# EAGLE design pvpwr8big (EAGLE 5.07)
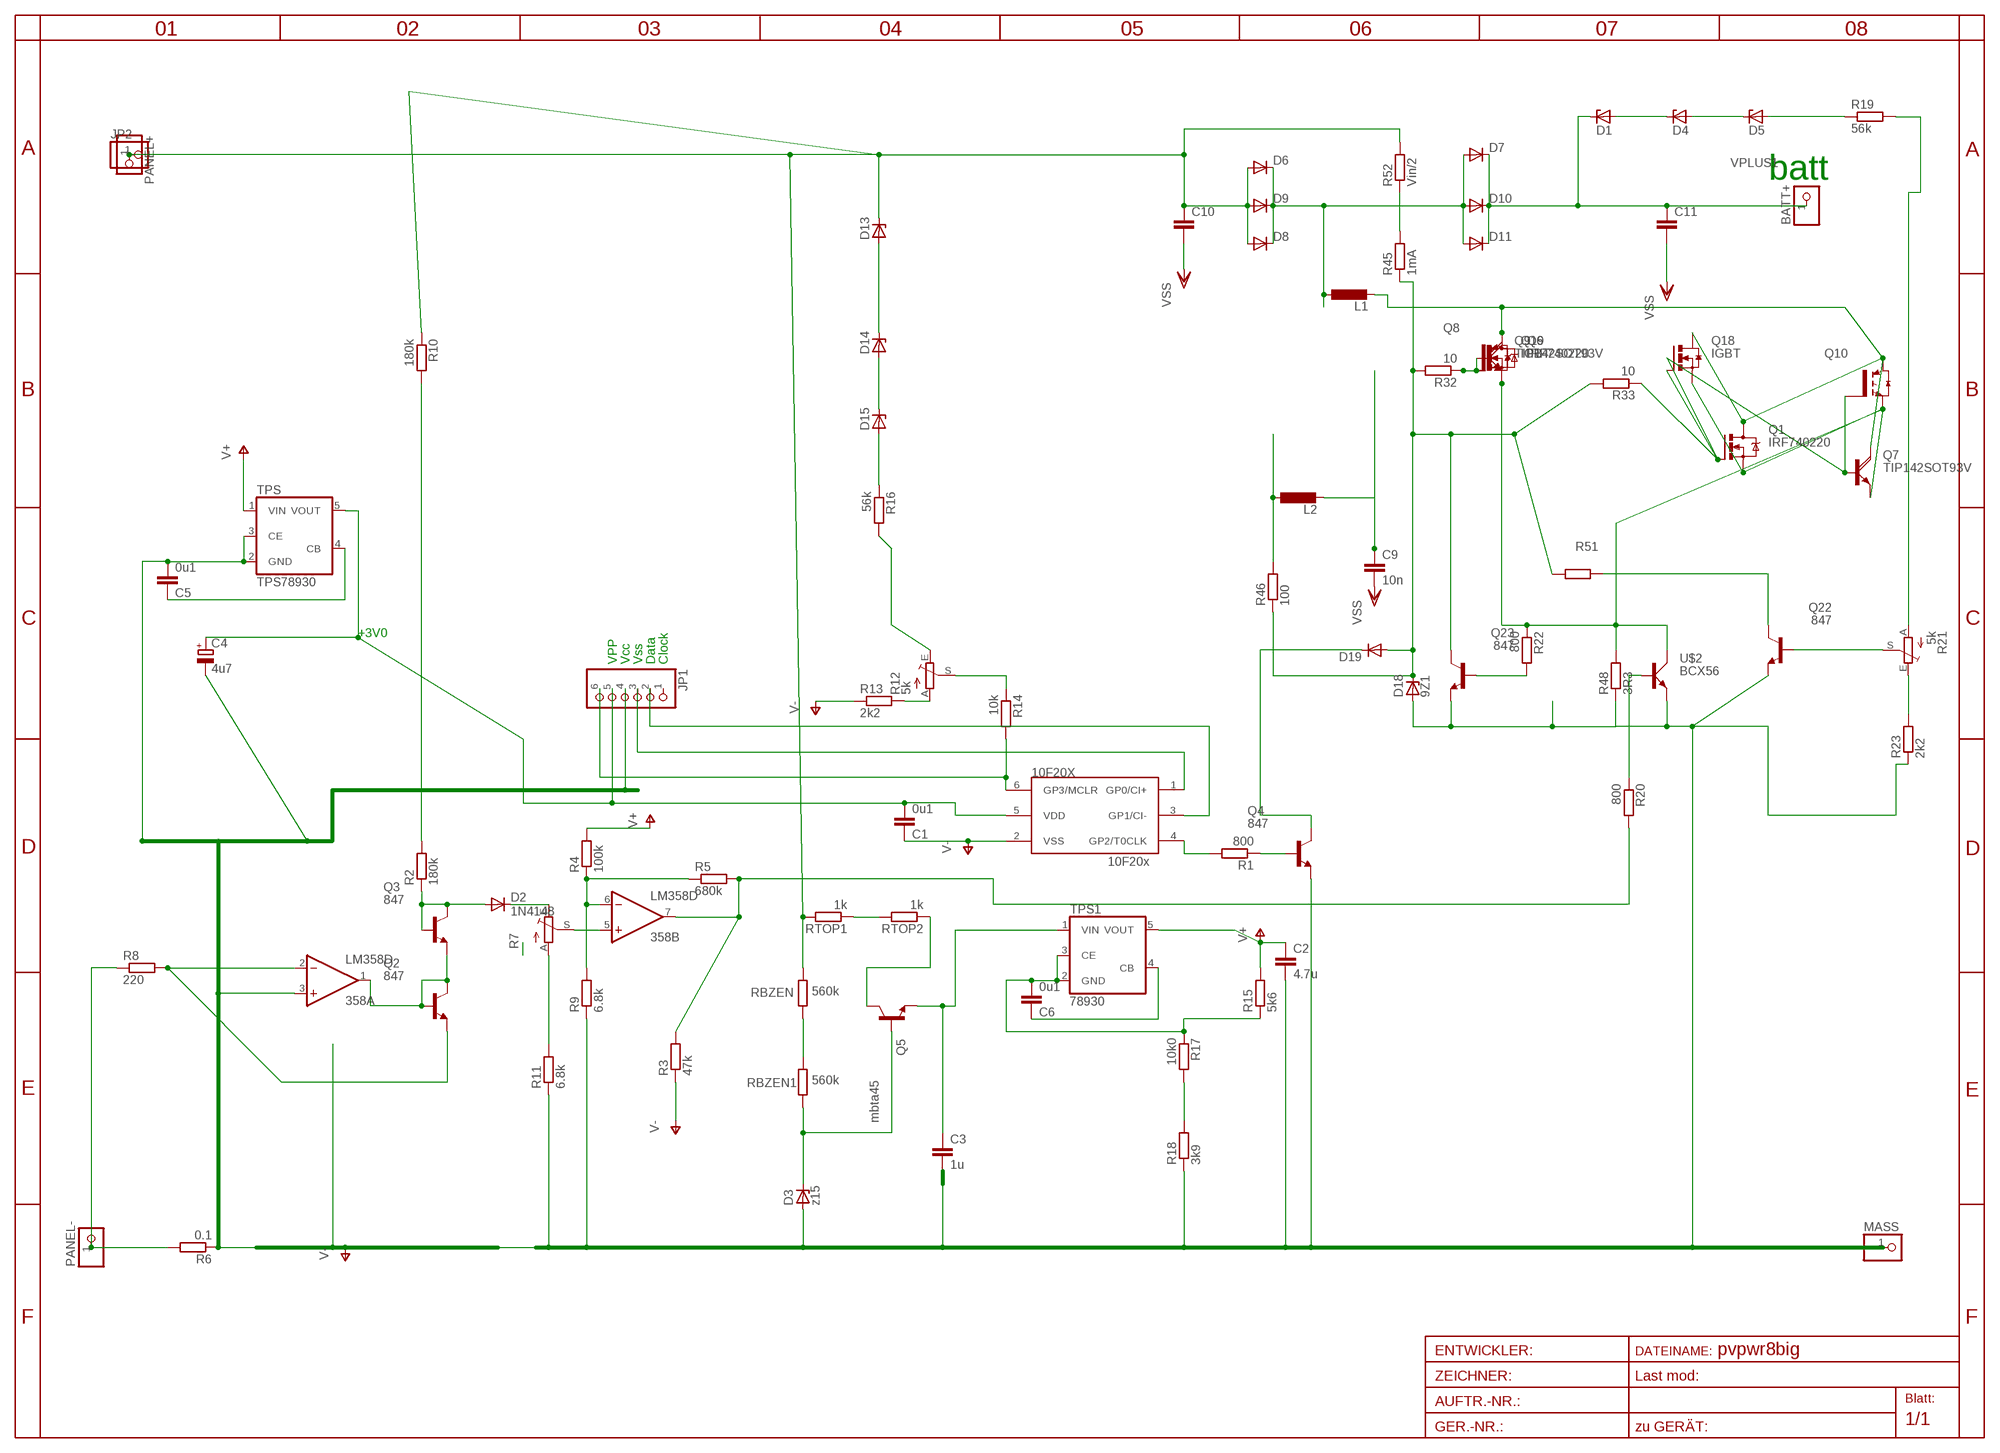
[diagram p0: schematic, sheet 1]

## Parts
10F20X  10F20x  PIC10F204OT  [SOT23-6]
358  LM358D  [SO08]
BATT+  PINHD-1X12MM2  [1X2MM2]
C1  0u1  C-EUC1206  [C1206]
C2  4.7u  C-EUC1206  [C1206]
C3  1u  C-EUC1206  [C1206]
C4  4u7  CPOL-EUSMCA  [SMC_A]
C5  0u1  C-EUC0805  [C0805]
C6  0u1  C-EUC0805  [C0805]
C9  10n  C-EUC0805  [C0805]
C10  C-EU075-052X106  [C075-052X106]
C11  C-EU075-052X106  [C075-052X106]
D1  ZENER-DIODESOD80C  [SOD80C]
D2  1N4148  DIODE-SOD80C  [SOD80C]
D3  z15  ZENER-DIODESOD80C  [SOD80C]
D4  ZENER-DIODESOD80C  [SOD80C]
D5  ZENER-DIODESOD80C  [SOD80C]
D6  DIODE-SMC  [SMC]
D7  DIODE-SMC  [SMC]
D8  DIODE-SMC  [SMC]
D9  DIODE-SMC  [SMC]
D10  DIODE-SMC  [SMC]
D11  DIODE-SMC  [SMC]
D13  ZENER-DIODESOD80C  [SOD80C]
D14  ZENER-DIODESOD80C  [SOD80C]
D15  ZENER-DIODESOD80C  [SOD80C]
D18  9Z1  ZENER-DIODESOD80C  [SOD80C]
D19  DIODE-MINIMELF  [MINIMELF]
JP1  PINHD-1X6  [1X06BOX]
JP2  PINHD-1X12MM2  [1X2MM2]
L1  L-EU4.13  [0204/13]
L2  L-EU0207/7  [0207/7]
MASS  PINHD-1X12MM2  [1X2MM2]
PANEL+  PINHD-1X11MM6  [1X1MM8]
PANEL-  PINHD-1X12MM2  [1X2MM2]
Q1  IRF740220  [TO220BV]
Q2  847  BC847ALT1SMD  [SOT23]
Q3  847  BC847ALT1SMD  [SOT23]
Q4  847  BC847ALT1SMD  [SOT23]
Q5  mbta45  BC847ALT1SMD  [SOT23]
Q6  IRF740220  [TO220BV]
Q7  TIP142SOT93V  [SOT93V]
Q8  IRG4BC15UD-S  [D2PACK]
Q9  TIP142SOT93V  [SOT93V]
Q10  IRG4BC15UD-S  [D2PACK]
Q18  IGBT  N-HEXFET_DPAK-  [TO252]
Q19  IGBT  N-HEXFET_DPAK-  [TO252]
Q22  847  BC847ASMD  [SOT23]
Q23  847  BC847ASMD  [SOT23]
R1  800  R-EU_R0805  [R0805]
R2  180k  R-EU_0207/15  [0207/15]
R3  47k  R-EU_R0805  [R0805]
R4  100k  R-EU_R1206  [R1206]
R5  680k  R-EU_R0805  [R0805]
R6  0.1  R-EU_R2512  [R2512]
R7  TRIM_EU-S64W  [S64W]
R8  220  R-EU_R0805  [R0805]
R9  6.8k  R-EU_R1206  [R1206]
R10  180k  R-EU_R1206  [R1206]
R11  6.8k  R-EU_R0805  [R0805]
R12  5k  TRIM_EU-S64W  [S64W]
R13  2k2  R-EU_R0805  [R0805]
R14  10k  R-EU_R0805  [R0805]
R15  5k6  R-EU_R0805  [R0805]
R16  56k  R-EU_R0805  [R0805]
R17  10k0  R-EU_R0805  [R0805]
R18  3k9  R-EU_R0805  [R0805]
R19  56k  R-EU_R0805  [R0805]
R20  800  R-EU_R0805  [R0805]
R21  5k  TRIM_EU-S64W  [S64W]
R22  800  R-EU_0207/12  [0207/12]
R23  2k2  R-EU_R0805  [R0805]
R32  10  R-EU_R0805  [R0805]
R33  10  R-EU_R0805  [R0805]
R45  1mA  R-EU_R1206  [R1206]
R46  100  R-EU_R0805  [R0805]
R48  3R3  R-EU_R2010  [R2010]
R51  39k  R-EU_R0805  [R0805]
R52  Vin/2  R-EU_R1206  [R1206]
RBZEN  560k  R-EU_R1206  [R1206]
RBZEN1  560k  R-EU_R1206  [R1206]
RTOP1  1k  R-EU_R1206  [R1206]
RTOP2  1k  R-EU_R1206  [R1206]
TPS  TPS78930  TPS78930SOT23-5  [SOT25]
TPS1  78930  TPS78930SOT23-5  [SOT25]
U$2  BCX56  [SOT223]

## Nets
BOOST_EN: D19.C Q4.3(C)
CB: D3.C Q5.1(B) RBZEN1.2
DQ18: L1.2 Q1.D Q6.D Q7.C Q8.2(C) Q9.C Q10.2(C) Q18.3(D) Q19.3(D)
GND1: C6.1 TPS1.4(CB)
IN-: PANEL-.1 R6.2 R8.1
N$1: Q4.1(B) R1.1
N$2: R7.A R11.2
N$4: 10F20X.1(GP0/CI+) JP1.3
N$5: 10F20X.4(GP2/T0CLK) R1.2
N$6: R2.2 R10.2
N$7: 358.1(A:OUT) Q2.1(B) Q2.3(C) Q3.2(E)
N$8: 10F20X.3(GP1/CI-) JP1.2
N$9: 10F20X.5(VDD) C1.2 C4.+ JP1.5 TPS.5(VOUT)
N$10: 358.2(A:-IN) Q2.2(E) R8.2
N$11: C5.1 TPS.4(CB)
N$12: D2.A Q3.1(B) Q3.3(C) R2.1
N$13: D2.C R7.E
N$15: 358.5(B:+IN) R7.S
N$16: Q5.3(C) RTOP2.1
N$17: 358.6(B:-IN) R4.1 R5.1 R9.2
N$18: D15.A R16.1
N$19: RBZEN1.1 RBZEN.2
N$20: D18.C D19.A Q23.3(C) R32.2 R33.2 R45.1 R46.1 R51.1
N$21: Q23.1(B) R22.2
N$22: D5.A R19.1
N$23: D14.A D15.C
N$24: D13.A D14.C
N$25: R12.E R16.2
N$26: R12.A R13.2
N$27: R12.S R14.1
N$28: R17.2 R18.2
N$29: RTOP1.1 RTOP2.2
N$30: D4.A D5.C
N$31: D1.A D4.C
N$32: R19.2 R21.A
N$33: 358.7(B:OUT) R3.2 R5.2 R20.2
N$34: R21.E R23.2
N$56: Q1.G Q7.B Q10.1(G) Q18.1(G) R33.1
N$58: Q6.G Q8.1(G) Q9.B Q19.1(G) R32.1
N$64: L2.1 R46.2
N$71: Q22.3(C) R51.2
N$74: C9.1 L2.2
N$80: R45.2 R52.1
N$89: R20.1 U$2.1(B)
NODOTL2: D6.C D7.A D8.C D9.C D10.A D11.A L1.1
PIR: 10F20X.6(GP3/MCLR) JP1.6 R14.2
PRB1: Q22.1(B) R21.S
SFET1: Q1.S Q6.S Q7.E Q8.3(E) Q9.E Q10.3(E) Q18.2(S) Q19.2(S) R22.1 R48.2 U$2.2(C)
V15: C3.1 Q5.2(E) TPS1.1(VIN)
V+: C2.1 R4.2 R15.2 TPS1.5(VOUT) TPS.1(VIN)
V-: 10F20X.2(VSS) 358.3(A:+IN) C1.1 C2.2 C3.2 C4.- C5.2 C9.2 C10.2 C11.2 D3.A D18.A JP1.4 MASS.1 Q4.2(E) Q22.2(E) Q23.2(E) R3.1 R6.1 R9.1 R11.1 R13.1 R18.1 R23.1 R48.1 TPS.2(GND) TPS.3(CE) U$2.3(E) ; supply symbol labelled VSS
VPLUS: C10.1 D6.A D8.A D9.A D13.C JP2.1 PANEL+.1 R10.1 R52.2 RBZEN.1 RTOP1.2
VPLUS1: BATT+.1 C11.1 D1.C D7.C D10.C D11.C
X: C6.2 R15.1 R17.1 TPS1.2(GND) TPS1.3(CE)
Unconnected: JP1.1

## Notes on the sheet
- batt
- +3V0
- VPP | Vcc | Vss | Data | Clock

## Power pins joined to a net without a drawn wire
V+: 358.8(P:V+)
V-: 358.4(P:V-)

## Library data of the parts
10F20X = microchip-3:PIC10F2*: uPC nW 0,25/0,5k Program Flash memory Comparator
358 = linear:LM358: OP AMP also LM158; LM258; LM2904 Source: http://cache.national.com/ds/LM/LM158.pdf
BATT+ JP2 MASS PANEL+ PANEL- = pinhead:PINHD-1X1: PIN HEADER
C1-C3 C5 C6 C9-C11 = rcl:C-EU: CAPACITOR, European symbol
C4 = rcl(2):CPOL-EU: POLARIZED CAPACITOR, European symbol
D1 D3-D5 D13-D15 D18 = diode:ZENER-DIODE: Z-Diode
D2 D6-D11 D19 = diode:DIODE-: DIODE
JP1 = pinhead:PINHD-1X6: PIN HEADER
L1 L2 = rcl:L-EU: INDUCTOR, European symbol
Q1 Q6 = transistor-power:IRF740: N-CHANNEL MOS FET
Q2-Q5 Q22 Q23 = transistor-npn:BC847*: NPN Transistor
Q7 Q9 = transistor-power:TIP142: NPN DARLINGTON TRANSISTOR
Q8 Q10 = transistor-power:IRG4BC15UD-: INSULATED GATE BIPOLAR TRANSISTOR WITH ULTRAFAST SOFT RECOVERY DIODE
Q18 Q19 = transistor-power:N-HEXFET_?-*: HEXFET® Power MOSFET
R1-R6 R8-R11 R13-R20 R22 R23 RBZEN RBZEN1 RTOP1 RTOP2 = rcl:R-EU_: RESISTOR, European symbol
R7 R12 R21 = pot:TRIM_EU-: POTENTIOMETER
R32 R33 R45 R46 R48 R51 R52 = rcl-2:R-EU_: RESISTOR, European symbol
TPS TPS1 = v-reg:TPS78930
U$2 = transistor-power:BCX56

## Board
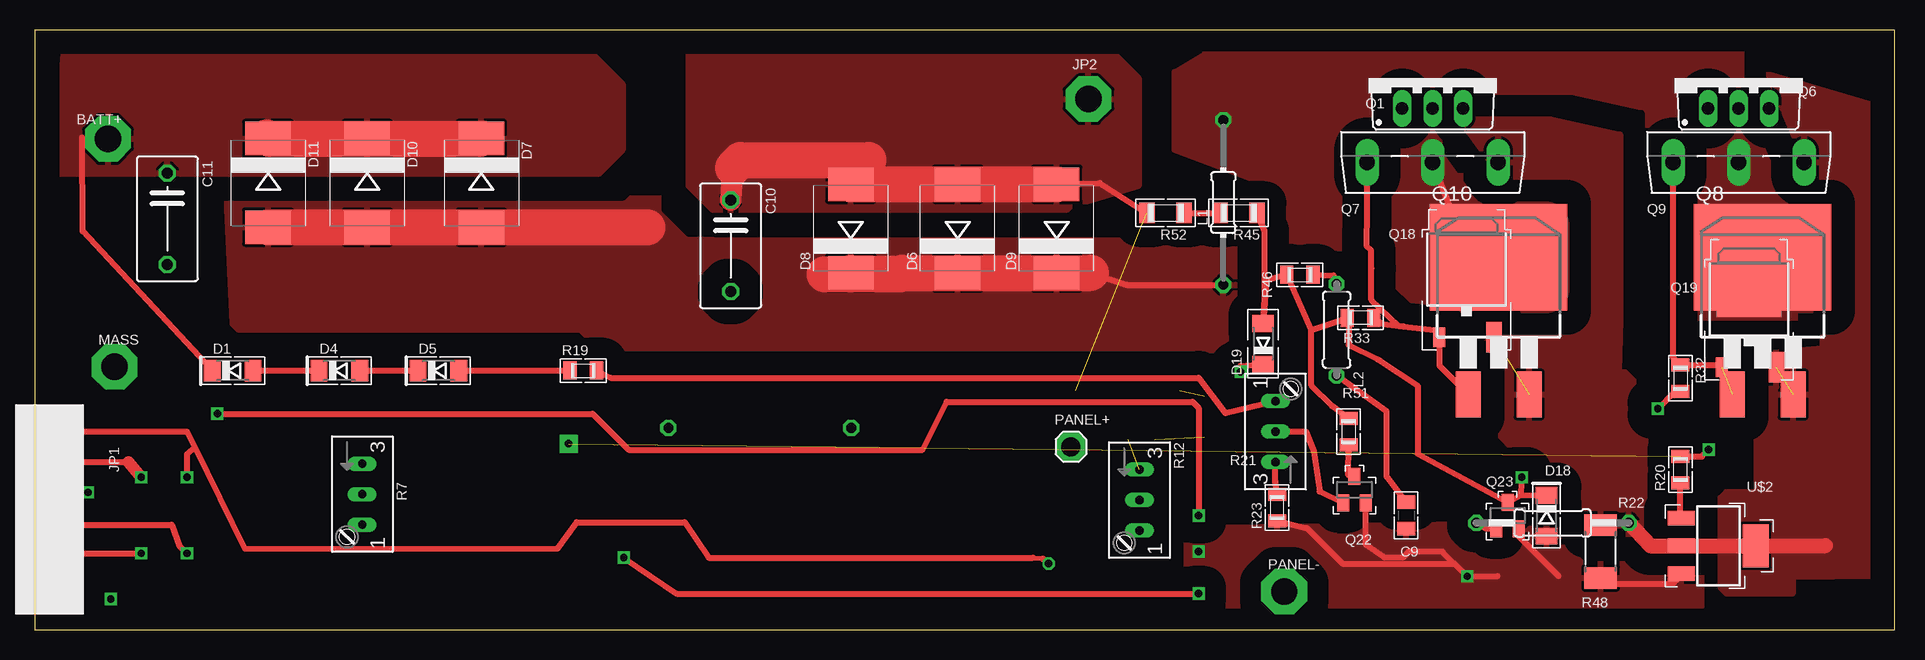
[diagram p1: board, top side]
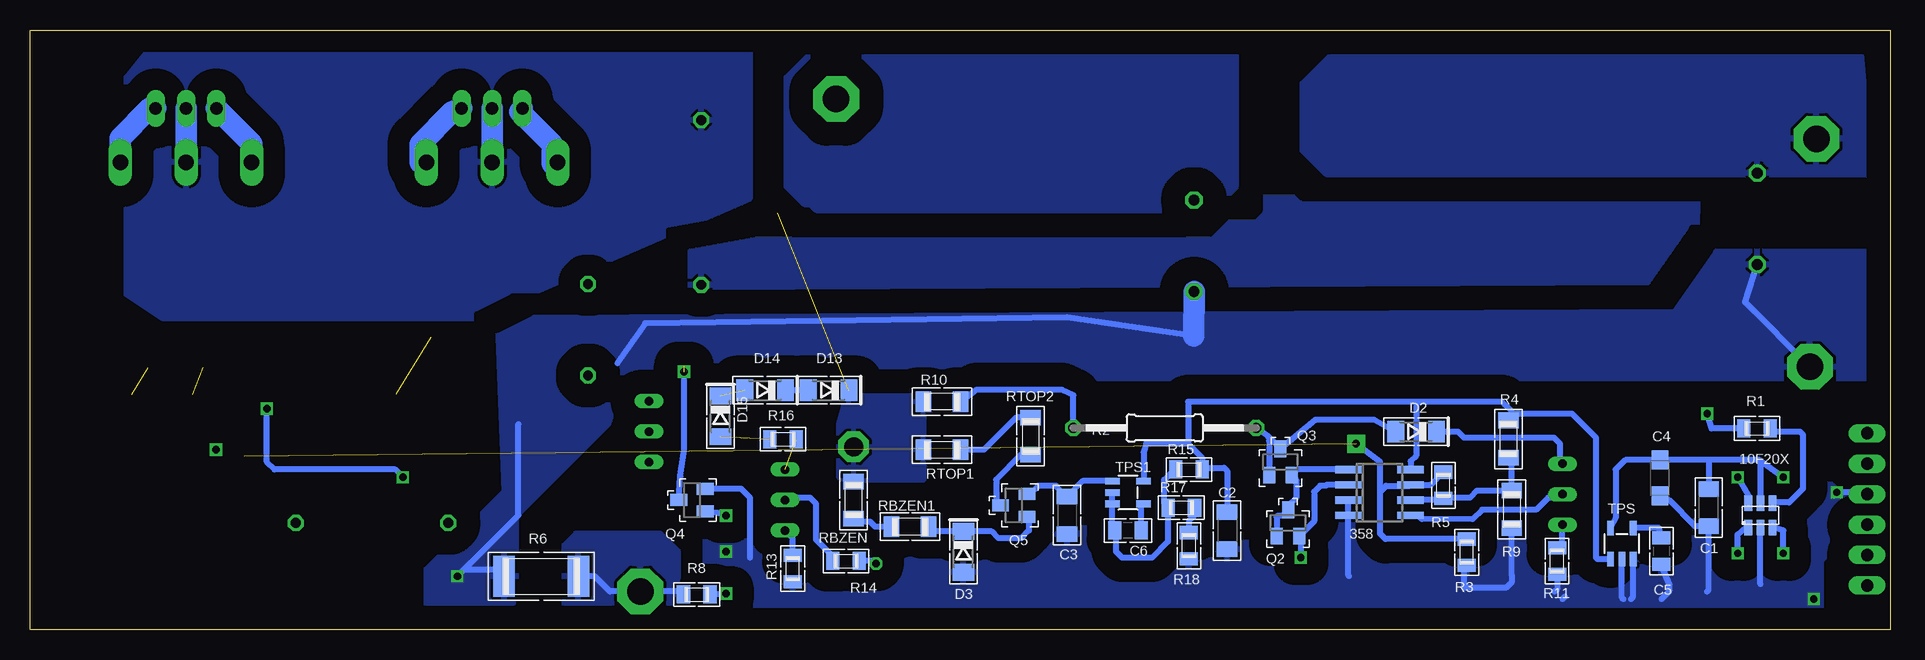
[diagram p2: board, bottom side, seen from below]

Size 155 x 50 mm. Coordinates in mm from the lower left corner, seen from the top.
Outline: 0,0 155,0 155,50 0,50 0,0
Copper layers (1*16): Top 0.035mm / dielectric 1.5mm / Bottom 0.035mm
Design rules "default *": minimum track width 10mil, minimum drill 24mil, track to track 8mil, track to pad 8mil, pad to pad 8mil, via to via 8mil, smd to smd 8mil, copper to edge 30mil, drill to drill 8mil, minimum pad ring 10mil, minimum via ring 8mil, stop-mask expansion 4mil, vias tented up to drill 0mil, thermal gap 10mil

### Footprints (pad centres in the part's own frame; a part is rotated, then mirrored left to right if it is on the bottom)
SOT23-6 = smd 0.635 x 1.27: 1 -1.016,-1.016; 2 0,-1.016; 3 1.016,-1.016; 4 1.016,1.016; 5 0,1.016; 6 -1.016,1.016
SO08 = smd 0.6 x 2.2: 1 -1.905,-2.6; 2 -0.635,-2.6; 3 0.635,-2.6; 4 1.905,-2.6; 5 1.905,2.6; 6 0.635,2.6; 7 -0.635,2.6; 8 -1.905,2.6
1X2MM2 = drill 2.2 pad 3.81 octagon: 1 0,0
C1206 = smd 1.3 x 1.7: 1 -1.55,0; 2 1.55,0
SMC_A = smd 1.6 x 1.4: + -1.5,0; - 1.5,0
C0805 = smd 1.1 x 1.5: 1 -1.1,0; 2 1.1,0
C075-052X106 = drill 0.914 octagon: 1 -3.81,0; 2 3.81,0
SOD80C = smd 1.4 x 1.8: A 1.7,0; C -1.7,0
SMC = smd 2.8 x 3.8: A 3.7,0; C -3.7,0
MINIMELF = smd 1.4 x 1.8: A 1.7,0; C -1.7,0
1X06BOX = drill 1.016 long: 1 -6.35,0; 2 -3.81,0; 3 -1.27,0; 4 1.27,0; 5 3.81,0; 6 6.35,0
0204/13 = drill 0.813 octagon: 1 -6.872,0; 2 6.872,0
0207/7 = drill 0.813 octagon: 1 -3.81,0; 2 3.81,0
1X1MM8 = drill 1.6 pad 2.54 octagon: 1 0,0
TO220BV = drill 1.016 long: D 0,-2.54; G -2.54,-2.54; S 2.54,-2.54
SOT23 = smd 1 x 1.4: 1 -0.95,-1.1; 2 0.95,-1.1; 3 0,1.1
SOT93V = drill 1.3 pad 1.676 long: B -5.461,-2.54; C 0,-2.54; E 5.461,-2.54
D2PACK = smd 2.083 x 3.81: 1 -2.54,-8.89; 3 2.54,-8.89 | smd 11.43 x 8.89: 2 0,2.54
TO252 = smd 1 x 1.6: 1 -2.28,-3.53 | smd 1.27 x 2.54: 2 2.28,-3.53 | smd 5.4 x 6.2: 3 0,3.77
R0805 = smd 1.1 x 1.5: 1 -1.1,0; 2 1.1,0
0207/15 = drill 0.813 octagon: 1 -7.62,0; 2 7.62,0
R1206 = smd 1.3 x 1.7: 1 -1.55,0; 2 1.55,0
R2512 = smd 1.8 x 3.4: 1 -3.1,0; 2 3.1,0
S64W = drill 0.7 long: A 2.54,1.27; E -2.54,1.27; S 0,1.27
0207/12 = drill 0.813 octagon: 1 -6.35,0; 2 6.35,0
R2010 = smd 1.8 x 2.7: 1 -2.2,0; 2 2.2,0
SOT25 = smd 0.55 x 1.2: 1 -0.95,-1.3; 2 0,-1.3; 3 0.95,-1.3; 4 0.95,1.3; 5 -0.95,1.3
SOT223 = smd 1.219 x 2.235: 1 -2.311,-3.099; 2 0,-3.099; 3 2.311,-3.099 | smd 3.6 x 2.2: 4 0,3.099

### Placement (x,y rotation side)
10F20X  10.79,9.53 0 bottom
358  42.55,11.43 270 bottom
BATT+  6.13,40.93 0 top
C1  15.11,10.16 90 bottom
C2  55.24,8.26 270 bottom
C3  68.58,9.53 270 bottom
C4  19.18,12.63 270 bottom
C5  19.05,6.54 270 bottom
C6  63.5,8.26 180 bottom
C9  114.3,9.53 270 top
C10  58,32 270 top
C11  11.06,34.25 270 top
D1  16.51,21.59 0 top
D2  39.5,16.5 180 bottom
D3  77.22,6.48 270 bottom
D4  25.4,21.59 0 top
D5  33.66,21.59 0 top
D6  76.92,33.44 90 top
D7  37.23,37.25 270 top
D8  68.03,33.44 90 top
D9  85.17,33.44 90 top
D10  27.71,37.25 270 top
D11  19.45,37.25 270 top
D13  88.46,19.95 180 bottom
D14  93.75,19.95 180 bottom
D15  97.47,17.78 270 bottom
D18  126,9.5 270 top
D19  102.38,23.83 90 top
JP1  1.91,10.02 90 top
JP2  87.82,44.24 0 top
L1  99.06,35.62 90 top
L2  108.5,25 270 top
MASS  6.67,21.91 0 top
PANEL+  86.36,15.24 0 top
PANEL-  104.14,3.17 0 top
Q1  116.5,46 0 top
Q2  50.16,8.89 0 bottom
Q3  50.8,13.97 0 bottom
Q4  99.83,10.79 90 bottom
Q5  73.03,10.35 90 bottom
Q6  142,46 0 top
Q7  116.5,41.5 0 top
Q8  144,28.5 0 top
Q9  142,41.5 0 top
Q10  122,28.5 0 top
Q18  119.34,27.9 0 top
Q19  142.88,25.4 0 top
Q22  109.99,11.66 0 top
Q23  122.75,9.5 0 top
R1  11.08,16.77 0 bottom
R2  60.44,16.81 180 bottom
R3  35.27,6.45 90 bottom
R4  31.8,15.88 90 bottom
R5  37.22,12.03 90 bottom
R6  112.39,4.45 0 bottom
R7  26.04,11.29 270 top
R8  99.44,2.92 0 bottom
R9  31.52,10.03 90 bottom
R10  79,19 0 bottom
R11  27.75,5.71 90 bottom
R12  90.81,10.79 270 top
R13  91.44,5.08 90 bottom
R14  87,5.71 0 bottom
R15  58.42,13.34 0 bottom
R16  92.25,15.88 0 bottom
R17  59.05,10.16 0 bottom
R18  58.42,6.99 90 bottom
R19  45.72,21.59 0 top
R20  137.16,13.34 90 top
R21  104.68,16.51 90 top
R22  126.5,8.89 180 top
R23  103.55,10.16 90 top
R32  137.16,20.95 270 top
R33  110.5,26 180 top
R45  100.33,34.75 180 top
R46  105.44,29.59 0 top
R48  130.5,6.5 90 top
R51  109.5,16.5 270 top
R52  94.25,34.75 180 top
RBZEN  86.36,10.79 270 bottom
RBZEN1  81.66,8.57 0 bottom
RTOP1  79,15 180 bottom
RTOP2  71.62,16.12 90 bottom
TPS  22.35,7.17 0 bottom
TPS1  63.5,11.43 270 bottom
U$2  140.34,6.99 270 top

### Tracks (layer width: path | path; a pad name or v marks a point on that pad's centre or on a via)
BOOST_EN  (via drill 0.6)  (1 unrouted)
  Top 0.5: 100.5,21.99 D19.C
  Bottom 0.5: Q4.3 100.8,12.79 100.5,15 v100.5,21.5
CB
  Bottom 0.5: Q5.1 71.75,9.23 71.75,8.26 72.39,7.62 74.3,7.62 74.85,8.18 D3.C 79.72,8.18 RBZEN1.2
DQ18
  Top 0.5: Q18.3 Q7.C
  Bottom 1.8: Q7.C Q1.D | Q9.C Q6.D
  pour Bottom (isolate 1.8, rank 4): 95,36 95,48.5 145,48.5 147,46 147,28 144,26 118,26
  pour Top (isolate 1.8, rank 4, no thermals): 95,40 95,46.5 97.5,48 145,48 147,46 148,26 103,26 103,37
G
  pour Bottom (isolate 2): 54.5,48 90,48 92,46 92,37 90.5,35.5 90,35.5 89.5,35 56.5,35 54.5,37
GND1
  Bottom 0.5: C6.1 62.4,10.28 TPS1.4
IN-
  Bottom 0.5: R6.2 107.95,4.45 106.68,3.17 PANEL-.1 100.8,3.17 R8.1
  pour Bottom (isolate 2): 101,3 101,6.5 102.5,8 109.5,8 110.5,7 110.5,1.5 110,1 101,1
N$1  (via drill 0.6)
  Top 0.5: v15.24,18 46.5,18 49.5,15 74,15 76,19 96.5,19 97,18.5 v97,9.5
  Bottom 0.5: R1.1 14.87,16.77 v15.24,18 | Q4.1 97.73,9.73 v97,9.5
N$2
  Bottom 0.5: R7.A 27.3,7.26 R11.2
N$4  (via drill 0.6)
  Top 0.5: JP1.3 11.43,8.75 12.06,6.99 v12.7,6.35
  Bottom 0.5: v12.7,6.35 12.7,7.9 11.99,8.51 10F20X.1
N$5
  Bottom 0.5: 10F20X.4 9.72,10.6 8.4,10.6 7.24,11.76 7.24,16.24 7.5,16.5 9.71,16.5 R1.2
N$6
  Bottom 0.5: R2.2 68.06,19.56 69,20 76.14,20 R10.2
N$7
  Bottom 0.5: 358.1 49.38,13.34 Q3.2 49.5,12.52 49.5,11 50.16,10.34 Q2.3 50.66,9.5 51,9.5 51.12,9.38 Q2.1
N$8  (via drill 0.6)
  Top 0.5: JP1.2 3.67,6.21 3.81,6.35 v8.89,6.35
  Bottom 0.5: v8.89,6.35 8.89,8.26 10F20X.3
N$9  (via drill 0.6)
  Top 0.5: 7.81,13.97 2.04,13.97 JP1.5
  Top 1.016: 7.81,13.97 v8.89,12.7
  Bottom 0.5: 15.24,14.13 10.86,14.13 10.75,14.02 | 15.24,14.13 C4.+ 22.06,14.13 22.86,13.34 22.86,9.3 TPS.5 | v8.89,12.7 10.7,13.97 10.75,14.02 | 10F20X.5 10.79,13.97 10.75,14.02 | C1.2 15.11,14 15.24,14.13
N$10  (via drill 0.6)
  Top 0.5: v97,3 53.5,3 v49.1,6
  Bottom 0.5: 358.2 46.94,12.06 47,12 47.5,12 48,11.5 48,9.01 Q2.2 49.1,7.41 v49.1,6 | R8.2 97.08,2.92 v97,3
N$11
  Bottom 0.5: TPS.4 19.25,8.47 C5.1
N$12
  Bottom 0.5: D2.A 43,17.5 47.88,17.5 Q3.3 51.62,15.88 | R2.1 51.82,16.09 51.62,15.88 | Q3.1 51.75,15.75 51.62,15.88
N$13
  Bottom 0.5: D2.C 35.99,16.49 35.5,16 28,16 27.5,15.5 27.5,14.03 R7.E
N$15
  Bottom 0.5: 358.5 39.52,9.53 39,9.2 34.77,9.22 34,10 29.5,10 28.5,11 27.59,11 R7.S
N$16
  Bottom 0.5: RTOP2.1 72.43,14.57 74.5,12.5 74.5,10.73 Q5.3
N$17
  Bottom 0.5: 358.6 37.35,10.79 R5.1 37.15,11 35,11 34.42,11.57 R9.2 31.52,14.05 R4.1
N$18  (1 unrouted)
N$19
  Bottom 0.5: RBZEN1.1 84.57,8.57 85,9 86.11,9 RBZEN.2
N$20  (via drill 0.6)
  Top 0.5: 123.89,11.22 D18.C | 123.89,11.22 Q23.3 115.25,14.66 115.25,20.34 112.09,22.44 arc7 111.9,22.55 109.5,23.75 109.5,25.4 R33.2 106.41,25 | R32.2 136.69,19.86 v135.25,18.41 | v123.92,12.7 123.92,12.26 123.89,11.22 | R51.1 108.12,18.64 106.41,20.36 106.41,25 | 106.41,25 R46.1 102.63,29.12 D19.A 102.5,27.65 102.5,33.25 R45.1
  Bottom 0.5: v135.25,18.41 135.25,13.97 134.62,13.34 124.56,13.34 v123.92,12.7
N$21
  Top 0.5: Q23.1 120.94,8.43 R22.2
N$22
  Top 0.5: D5.A R19.1
N$23  (1 unrouted)
N$24
  Bottom 0.5: D13.A D14.C
N$25  (1 unrouted)
N$26
  Bottom 0.5: R13.2 91.44,7.62 R12.A
N$27
  Bottom 0.5: R14.1 88.09,6.09 89.5,7.5 89.5,10.5 90,11 91.87,11 R12.S
N$28
  Bottom 0.5: R18.2 58.42,9.08 58,9.5 58,10.12 R17.2
N$29
  Bottom 0.5: RTOP1.1 75.52,14.98 72.83,17.67 RTOP2.2
N$30
  Top 0.5: D4.A D5.C
N$31
  Top 0.5: D1.A D4.C
N$32
  Top 0.5: R21.A 99.23,18.05 97,21 48,21 R19.2
N$33  (via drill 0.6, 0.6 pad 1.5)  (1 unrouted)
  Top 0.5: R20.2 138.94,14.44 v139.5,15
  Bottom 0.5: R5.2 38.28,12.06 358.7 40.01,12 42,12 42.5,11.5 | R3.2 42.05,7.54 42.5,8 42.5,11.5 | 42.5,11.5 42.5,14 v44.5,15.5
N$34
  Top 0.5: R21.E 103.41,12.39 R23.2
N$56
  Top 0.5: Q7.B 111.04,34.96 111,32 111.38,31.63 111.39,30.11 111.39,27.5 113.7,25.31 | 113.7,25.31 114.14,25.25 112.39,25.5 R33.1 | 113.7,25.31 117.06,24.95 Q18.1 117.06,22.01 Q10.1
  Bottom 1.8: Q1.G 114.18,43.18 111.5,40.5 111.5,38.86 Q7.B
N$58  (1 unrouted)
  Top 0.5: Q19.1 140.41,22.05 R32.1 136.54,22.68 Q9.B
  Bottom 1.8: Q9.B 136.54,40.54 Q6.G
N$64
  Top 0.5: R46.2 108.24,29.54 L2.1
N$71
  Top 0.5: Q22.3 109.49,12.87 R51.2
N$74
  Top 0.5: L2.2 112.67,18.21 112.67,12.76 C9.1
N$80
  Top 0.5: R52.1 R45.2
N$89
  Top 0.5: R20.1 137.16,9.37 U$2.1
NODOTL2
  Top 0.5: L1.1 91.04,28.74 88.03,29.74
  Top 3: D11.A D10.A D7.A 51.09,33.55 | 65.81,29.63 71.64,29.63 | 71.64,29.63 72.16,29.63 72.27,29.74 D6.C D9.C 88.03,29.74 | 71.64,29.63 D8.C
  pour Top (isolate 2, rank 3): 16,36 53,36 56.5,32.5 94.5,32.5 100,32 100,24 93.5,21.5 49,21.5 45.5,25 17,25 16.5,25.5
  pour Bottom (isolate 2, rank 3): 16,36 53,36 56.5,32.5 94.5,32.5 100,31.5 100,23.5 93.5,21.5 49,21.5 45.5,25 17,25 16.5,25.5
PIR  (via drill 0.6, 0.6 pad 1)
  Top 0.406: 83.19,5.98 84,5.93 v84.5,5.5
  Top 0.5: 83.19,5.98 56.17,5.98 54.17,8.95 45.17,8.95 43.58,6.77 17.54,6.74 13.34,15.24 | 13.34,15.24 12.7,16.51 2.04,16.51 JP1.6 | v12.7,12.7 12.7,14.61 13.34,15.24 | v84.5,5.5 84.02,5.91 84,5.93
  Bottom 0.5: 10F20X.6 11.81,11.18 v12.7,12.7 | R14.2 84.58,5.71 v84.5,5.5
PRB1
  Top 0.5: R21.S 105.95,16.51 106.58,14.88 107.08,11.52 Q22.1
SFET1  (2 unrouted)
  Top 1.27: 149.22,6.99 U$2.2 134.62,6.99 R22.1
  Bottom 1.8: Q1.S 119.82,43.18 122.5,40.5 122.5,38.93 Q7.E | Q6.S 145.04,43.46 147.5,41 147.5,39 Q9.E
  pour Top (isolate 2, rank 3): 129.54,10.16 142.88,10.16 143.51,10.79 143.5,22.5 143.5,23 149,23.5 149.01,35.51 144.51,46.31 153.03,43.81 153.67,26.04 153.67,4.45 142.53,4.31 136.53,6.35 129.54,6.35
  pour Top (isolate 2, rank 3): 118.75,42.55 126.36,42.55 132.13,41.27 132.13,25.86 132,21.5 132.5,21.5 134.5,19.5 133.99,7.62 130.18,7.62 118.75,19.68 118.75,21.75 124,27 124,35.5 123.5,36
  pour Top (rank 3, no thermals): 140.5,10 140.5,11 141,11.5 146,11.5 146.5,11 146.5,3 141,3 140.5,3.5
V15
  Bottom 0.5: TPS1.1 67.28,12.38 C3.1 69.5,12 71,12 71.7,11.3 Q5.2
V+
  Bottom 0.5: TPS.1 24.38,5.88 24.5,6 24.5,16 26.5,18 31.5,18 31.5,18.18 | 31.5,18.18 R4.2 | 39.5,19 32.32,19 31.5,18.18 | 39.5,19 58.5,19 58.5,15.5 | C2.1 55.24,13.24 55.5,13.5 57.16,13.5 R15.2 57.32,14.32 58.5,15.5 | TPS1.5 62.2,14.8 62,15.5 58.5,15.5 | 358.8 39.95,14.05 39.5,14.5 39.5,19
V-  (via drill 0.6)
  Top 0.5: Q23.2 123.5,7.94 127,4.45 | U$2.3 137.24,4.52 136.53,3.81 130.51,3.81 R48.1 | v119.38,4.45 121.92,4.45 | JP1.4 2.04,11.43 | v4.45,11.43 1.91,11.43 | Q22.2 110.94,7.06 112.5,6 114,6 114.5,6.5 117.33,6.5 v119.38,4.45 | R23.1 106.05,8.46 109,5.5 118.33,5.5 v119.38,4.45
  Bottom 0.5: 7.62,20.95 MASS.1 12.06,27.3 C11.2 | R6.1 114.94,5 118.82,5 v119.38,4.45 114.3,9.53 114.3,17.14 | 58.04,24.5 68.58,26.04 103.73,25.54 106.05,22.23 | 15.24,3.17 15.11,3.31 C1.1 16.23,8.62 18.41,10.79 18.84,10.79 C4.- | 10.79,3.81 10F20X.2 | C5.2 18.41,3.81 18.41,3.17 19.05,2.54 | 27.08,2.77 27.3,2.54 | TPS.3 21.4,2.73 21.59,2.54 | 22.23,2.54 22.35,2.67 TPS.2 | R11.1 27.75,3.37 27.94,3.17 | 45.09,4.45 45.15,4.5 358.4 358.3 | 95,6 95,11 95.75,11.74 Q4.2 | v4.45,11.43 2.04,11.43 JP1.4 | R9.1 31.52,4.53 31.5,4.5 31.5,4 32,3.5 35.5,3.5 35.5,5.12 R3.1
  Bottom 1.8: 58.04,24.5 C10.2
  other vias: 6.35,2.54 97,6.5
  pour Top (isolate 1.8, rank 2): 96,8.5 125.73,8.89 128.5,6 129,5.5 138.5,5.5 138.89,5.11 138.89,1.91 96,2
  pour Bottom (isolate 1.8, rank 2): 1.27,12.06 6.35,12.06 7.62,10.79 7.62,9.53 8.89,8.26 11.43,8.26 11.43,6.99 13.34,9 106.72,9 106.68,3.81 106.68,-0.64 106.05,-1.27 8.26,-1.27 5.71,1.27 5.71,5.71 5.08,6.35
  pour Bottom (isolate 2, rank 2): 18,26.5 113,26 116,24.5 115.5,11.5 122,5 122,2 115,2 114.5,2.5 114.5,9.5 103,21 1,21 0,22 0,25.5 0.5,31.5 14.5,31.5
VPLUS  (1 unrouted)
  Top 0.5: R52.2 88.78,37.25 D9.A
  Top 1.8: C10.1 58.19,38.52
  Top 3: 58.19,38.52 58.83,39.16 69.51,39.16 D8.A D6.A D9.A
  pour Bottom (isolate 2): 80.5,19.5 87,19.5 87.63,17.14 87.63,12.7 87,12.5 80.5,12.5
  pour Top (isolate 2): 54.5,48 90,48 92,46 92,37 87,35.5 86.5,35.5 86,35 56.5,35 54.5,37
VPLUS1
  Top 0.5: D1.C 4.01,33.22 3.97,41.06
  Top 3: 19.34,41.06 D11.C D10.C D7.C
  pour Top (isolate 2): 2.5,49 45.5,49 49,45.5 49,40 47,38 2,38 1.5,37.5
  pour Bottom (isolate 2): 2.5,49 45.5,49 49,45.5 49,40 47,38 2,38 1.5,37.5
X
  Bottom 0.5: R15.1 59.66,13.34 60.5,12.5 60.5,10.51 R17.1 60.16,7.34 61.5,6 64,6 64.5,6.5 64.5,8.15 C6.2 64.8,8.46 TPS1.3 TPS1.2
